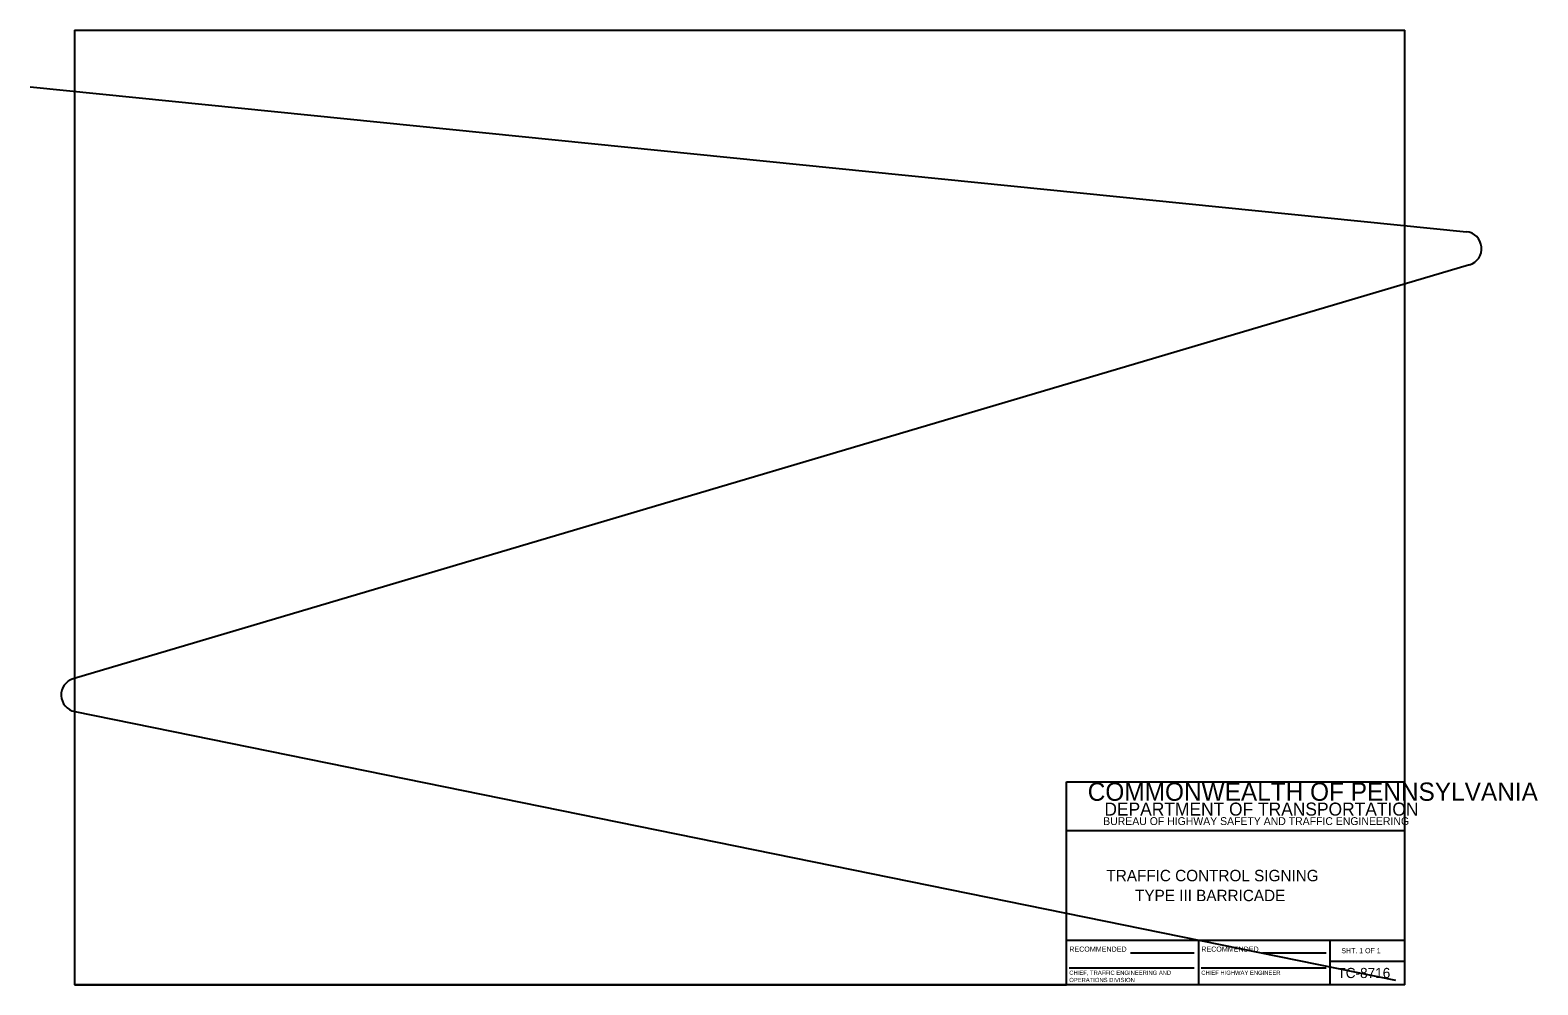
# Model space of a CAD drawing. Extents: x 641885 to 642934, y 293121 to 294294.
# Drawn here: x 641899 to 642790, y 293121 to 293685 of the extents above; entities that cross this region are included whole.
import ezdxf

# ---------------------------------------------------------------- set-up
doc = ezdxf.new("R2010")
doc.units = 0
doc.layers.add('Level 1', color=7, linetype='Continuous')
doc.layers.add('Level 2', color=7, linetype='Continuous')

msp = doc.modelspace()

# ---------------------------------------------------------------- linework, layer by layer
at = {"layer": 'Level 1'}
for p, q in [((641925.31, 293684.63), (642711.31, 293684.63)), ((641925.31, 293684.63), (641925.31, 293120.63)), ((642711.31, 293120.63), (642711.31, 293684.63)), ((642511.31, 293120.63), (642511.31, 293240.63)), ((642511.31, 293240.63), (642711.31, 293240.63)), ((642711.31, 293211.63), (642511.31, 293211.63)), ((642511.31, 293147), (642711.31, 293147)), ((642549.24, 293139.57), (642586.87, 293139.57)), ((642589.31, 293147), (642589.31, 293120.63)), ((642627.24, 293139.57), (642664.87, 293139.57)), ((642667.19, 293120.63), (642667.19, 293147)), ((642512.99, 293130.68), (642586.87, 293130.68)), ((642590.99, 293130.68), (642664.87, 293130.68)), ((642667.19, 293134.63), (642711.31, 293134.63)), ((642711.31, 293120.63), (641925.31, 293120.63)), ((641925.31, 293120.63), (642511.31, 293120.63))]:
    msp.add_line(p, q, dxfattribs=at)
at = {"layer": 'Level 2'}
for p, q in [((641899.02, 293651.19), (642747.64, 293565.54)), ((642749.47, 293546), (641924.52, 293301.44)), ((641925.36, 293282.06), (642705.67, 293123.37))]:
    msp.add_line(p, q, dxfattribs=at)
for centre, start, end in [((642746.63, 293555.59), 286.5125, 84.23683), ((641927.36, 293291.86), 106.5125, 258.50456)]:
    msp.add_arc(centre, 10, start, end, dxfattribs=at)

# ---------------------------------------------------------------- texts
at = {"layer": 'Level 1'}
for s, height, p in [('COMMONWEALTH OF PENNSYLVANIA', 10.7828, (642523.9, 293229.36)), ('DEPARTMENT OF TRANSPORTATION', 7.6837, (642533.76, 293220.61)), ('BUREAU OF HIGHWAY SAFETY AND TRAFFIC ENGINEERING', 4.6253, (642533.04, 293215.04)), ('TRAFFIC CONTROL SIGNING', 6.75, (642534.96, 293181.81)), ('TYPE III BARRICADE', 6.75, (642551.86, 293170.06)), ('RECOMMENDED', 3.048, (642512.99, 293140.2)), ('RECOMMENDED', 3.048, (642590.99, 293140.2)), ('SHT. 1 OF 1', 3, (642673.74, 293139.31)), ('TC-8716', 6, (642671.45, 293124.63)), ('OPERATIONS DIVISION', 2.5, (642512.99, 293122.26)), ('CHIEF, TRAFFIC ENGINEERING AND', 2.5, (642512.99, 293126.51)), ('CHIEF HIGHWAY ENGINEER', 2.5, (642590.99, 293126.51))]:
    msp.add_text(s, height=height, dxfattribs=at).set_placement(p)

doc.saveas('drawing.dxf')
